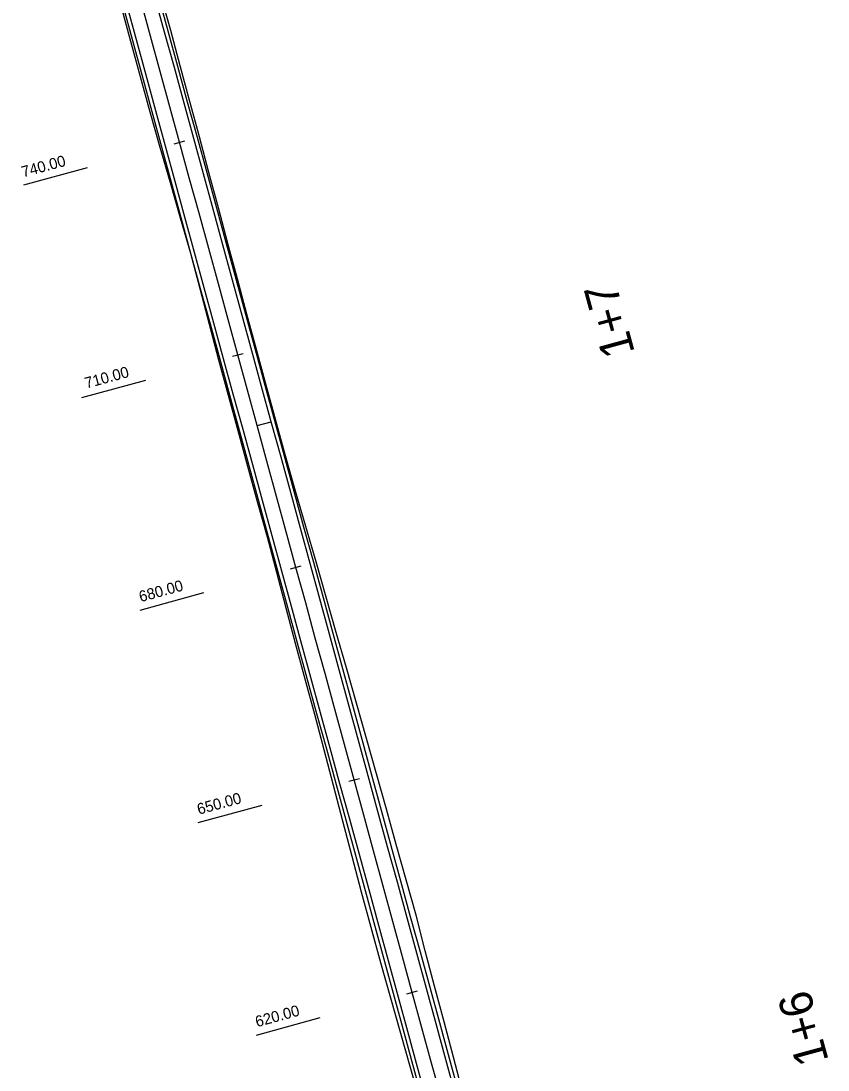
# Model space of a CAD drawing. Extents: x -550605 to -538780, y -1102367 to -1093705.
# Drawn here: x -547518.8 to -547408.9, y -1100657.2 to -1100514.3 of the extents above; entities that cross this region are included whole.
import ezdxf

# ---------------------------------------------------------------- set-up
doc = ezdxf.new("R2010")
doc.units = 0
for name, color, linetype in [('SIT - hrany vozovky', 7, 'Continuous'), ('SIT - osa cesty', 7, 'Continuous'), ('SIT - paty násypů', 7, 'Continuous'), ('SIT - staničení po 100m', 7, 'Continuous'), ('SIT - staničení po 30m', 7, 'Continuous')]:
    doc.layers.add(name, color=color, linetype=linetype)

msp = doc.modelspace()

# ---------------------------------------------------------------- linework, layer by layer
at = {"layer": 'SIT - hrany vozovky'}
for points in [[(-547459.65, -1100660.52), (-547460.97, -1100655.7), (-547462.29, -1100650.88), (-547463.61, -1100646.05), (-547464.93, -1100641.23), (-547466.25, -1100636.41), (-547467.57, -1100631.59), (-547468.89, -1100626.76), (-547470.21, -1100621.94), (-547471.53, -1100617.12), (-547472.85, -1100612.3), (-547474.17, -1100607.47), (-547475.49, -1100602.65), (-547476.81, -1100597.83), (-547478.13, -1100593), (-547479.45, -1100588.18), (-547480.77, -1100583.36), (-547482.09, -1100578.54), (-547483.41, -1100573.71), (-547484.73, -1100568.89), (-547486.05, -1100564.07), (-547487.37, -1100559.25), (-547488.69, -1100554.42), (-547490.01, -1100549.6), (-547491.33, -1100544.78), (-547492.65, -1100539.96), (-547493.97, -1100535.13), (-547495.29, -1100530.31), (-547496.61, -1100525.49), (-547497.93, -1100520.67), (-547499.25, -1100515.84), (-547500.57, -1100511.02)], [(-547459.16, -1100660.39), (-547460.48, -1100655.57), (-547461.8, -1100650.74), (-547463.12, -1100645.92), (-547464.44, -1100641.1), (-547465.76, -1100636.28), (-547467.08, -1100631.45), (-547468.4, -1100626.63), (-547469.72, -1100621.81), (-547471.04, -1100616.99), (-547472.36, -1100612.16), (-547473.68, -1100607.34), (-547475, -1100602.52), (-547476.32, -1100597.7), (-547477.64, -1100592.87), (-547478.96, -1100588.05), (-547480.28, -1100583.23), (-547481.6, -1100578.4), (-547482.92, -1100573.58), (-547484.24, -1100568.76), (-547485.56, -1100563.94), (-547486.88, -1100559.11), (-547488.2, -1100554.29), (-547489.52, -1100549.47), (-547490.84, -1100544.65), (-547492.16, -1100539.82), (-547493.48, -1100535), (-547494.8, -1100530.18), (-547496.12, -1100525.36), (-547497.44, -1100520.53), (-547498.76, -1100515.71), (-547500.08, -1100510.89)], [(-547463.99, -1100661.71), (-547465.31, -1100656.89), (-547466.63, -1100652.06), (-547467.95, -1100647.24), (-547469.27, -1100642.42), (-547470.59, -1100637.6), (-547471.91, -1100632.77), (-547473.23, -1100627.95), (-547474.55, -1100623.13), (-547475.87, -1100618.31), (-547477.19, -1100613.48), (-547478.51, -1100608.66), (-547479.83, -1100603.84), (-547481.15, -1100599.02), (-547482.47, -1100594.19), (-547483.79, -1100589.37), (-547485.11, -1100584.55), (-547486.43, -1100579.72), (-547487.75, -1100574.9), (-547489.07, -1100570.08), (-547490.39, -1100565.26), (-547491.71, -1100560.43), (-547493.03, -1100555.61), (-547494.35, -1100550.79), (-547495.67, -1100545.97), (-547496.99, -1100541.14), (-547498.31, -1100536.32), (-547499.63, -1100531.5), (-547500.95, -1100526.68), (-547502.27, -1100521.85), (-547503.59, -1100517.03), (-547504.91, -1100512.21)], [(-547463.5, -1100661.58), (-547464.82, -1100656.75), (-547466.14, -1100651.93), (-547467.46, -1100647.11), (-547468.78, -1100642.29), (-547470.1, -1100637.46), (-547471.42, -1100632.64), (-547472.74, -1100627.82), (-547474.06, -1100623), (-547475.38, -1100618.17), (-547476.7, -1100613.35), (-547478.02, -1100608.53), (-547479.34, -1100603.71), (-547480.66, -1100598.88), (-547481.98, -1100594.06), (-547483.3, -1100589.24), (-547484.62, -1100584.42), (-547485.94, -1100579.59), (-547487.26, -1100574.77), (-547488.58, -1100569.95), (-547489.9, -1100565.12), (-547491.22, -1100560.3), (-547492.54, -1100555.48), (-547493.86, -1100550.66), (-547495.18, -1100545.83), (-547496.5, -1100541.01), (-547497.82, -1100536.19), (-547499.14, -1100531.37), (-547500.46, -1100526.54), (-547501.78, -1100521.72), (-547503.1, -1100516.9), (-547504.42, -1100512.08)]]:
    msp.add_lwpolyline(points, dxfattribs=at)
at = {"layer": 'SIT - osa cesty'}
msp.add_lwpolyline([(-547461.58, -1100661.05), (-547462.9, -1100656.23), (-547464.22, -1100651.4), (-547465.54, -1100646.58), (-547466.86, -1100641.76), (-547468.18, -1100636.94), (-547469.5, -1100632.11), (-547470.82, -1100627.29), (-547472.14, -1100622.47), (-547473.46, -1100617.65), (-547474.78, -1100612.82), (-547476.1, -1100608), (-547477.42, -1100603.18), (-547478.74, -1100598.36), (-547480.05, -1100593.53), (-547481.37, -1100588.71), (-547482.69, -1100583.89), (-547484.01, -1100579.06), (-547485.33, -1100574.24), (-547486.65, -1100569.42), (-547487.97, -1100564.6), (-547489.29, -1100559.77), (-547490.61, -1100554.95), (-547491.93, -1100550.13), (-547493.25, -1100545.31), (-547494.57, -1100540.48), (-547495.89, -1100535.66), (-547497.21, -1100530.84), (-547498.53, -1100526.02), (-547499.85, -1100521.19), (-547501.17, -1100516.37), (-547502.49, -1100511.55)], dxfattribs=at)
at = {"layer": 'SIT - paty násypů'}
for points in [[(-547458.66, -1100660.25), (-547459.94, -1100655.42), (-547461.22, -1100650.58), (-547462.5, -1100645.75), (-547463.78, -1100640.92), (-547465.03, -1100636.07), (-547466.37, -1100631.26), (-547467.72, -1100626.44), (-547469.07, -1100621.63), (-547470.42, -1100616.81), (-547471.77, -1100612), (-547473.12, -1100607.19), (-547474.5, -1100602.38), (-547475.88, -1100597.57), (-547477.26, -1100592.77), (-547478.64, -1100587.96), (-547480.01, -1100583.15), (-547481.44, -1100578.36), (-547482.81, -1100573.55), (-547484.11, -1100568.72), (-547485.42, -1100563.9), (-547486.73, -1100559.07), (-547488.04, -1100554.25), (-547489.34, -1100549.42), (-547490.66, -1100544.6), (-547491.94, -1100539.76), (-547493.23, -1100534.93), (-547494.51, -1100530.1), (-547495.8, -1100525.27), (-547497.12, -1100520.44), (-547498.43, -1100515.62), (-547499.75, -1100510.8)], [(-547464.37, -1100661.81), (-547465.73, -1100657), (-547467.09, -1100652.19), (-547468.44, -1100647.38), (-547469.8, -1100642.56), (-547471.14, -1100637.75), (-547472.44, -1100632.92), (-547473.73, -1100628.09), (-547475.01, -1100623.26), (-547476.28, -1100618.42), (-547477.55, -1100613.58), (-547478.82, -1100608.75), (-547480.12, -1100603.92), (-547481.42, -1100599.09), (-547482.71, -1100594.26), (-547483.98, -1100589.42), (-547485.26, -1100584.59), (-547486.62, -1100579.78), (-547487.94, -1100574.96), (-547489.25, -1100570.13), (-547490.56, -1100565.3), (-547491.86, -1100560.48), (-547493.14, -1100555.64), (-547494.42, -1100550.81), (-547495.7, -1100545.98), (-547497.08, -1100541.17), (-547498.46, -1100536.36), (-547499.84, -1100531.56), (-547501.21, -1100526.75), (-547502.55, -1100521.93), (-547503.86, -1100517.11), (-547505.17, -1100512.28)]]:
    msp.add_lwpolyline(points, dxfattribs=at)
at = {"layer": 'SIT - staničení po 100m'}
msp.add_lwpolyline([(-547486.65, -1100569.42), (-547484.73, -1100568.89)], dxfattribs=at)
at = {"layer": 'SIT - staničení po 30m'}
for points in [[(-547497.94, -1100531.04), (-547496.49, -1100530.64)], [(-547518.43, -1100536.65), (-547509.75, -1100534.27)], [(-547490.02, -1100559.97), (-547488.57, -1100559.58)], [(-547510.51, -1100565.58), (-547501.83, -1100563.21)], [(-547482.1, -1100588.91), (-547480.65, -1100588.51)], [(-547502.59, -1100594.52), (-547493.91, -1100592.14)], [(-547474.18, -1100617.84), (-547472.73, -1100617.45)], [(-547494.67, -1100623.45), (-547485.99, -1100621.08)], [(-547466.26, -1100646.78), (-547464.81, -1100646.38)], [(-547486.76, -1100652.39), (-547478.07, -1100650.01)]]:
    msp.add_lwpolyline(points, dxfattribs=at)

# ---------------------------------------------------------------- texts
at = {"layer": 'SIT - staničení po 100m'}
for s, p in [('1+7', (-547435.21, -1100559.45)), ('1+6', (-547408.82, -1100655.87))]:
    msp.add_text(s, height=4.5, rotation=105.307, dxfattribs=at).set_placement(p)
at = {"layer": 'SIT - staničení po 30m'}
for s, p in [('740.00', (-547518.51, -1100535.63)), ('710.00', (-547509.9, -1100564.38)), ('680.00', (-547502.52, -1100593.46)), ('650.00', (-547494.6, -1100622.4)), ('620.00', (-547486.68, -1100651.33))]:
    msp.add_text(s, height=1.5, rotation=15.307, dxfattribs=at).set_placement(p)

doc.saveas('drawing.dxf')
